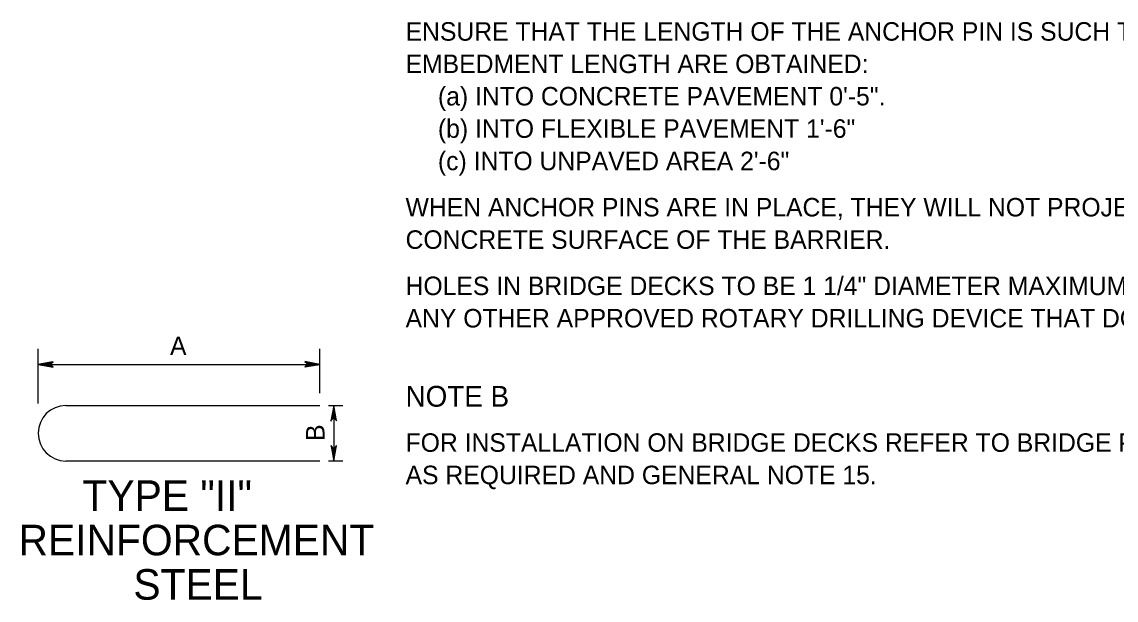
# Model space of a CAD drawing. Extents: x 499866 to 500993, y 499985 to 500645.
# Drawn here: x 500570.3 to 500807.1, y 500188.6 to 500313.6 of the extents above; entities that cross this region are included whole.
import ezdxf

# ---------------------------------------------------------------- set-up
doc = ezdxf.new("R2010")
doc.units = 0
doc.layers.add('24', color=7, linetype='Continuous')
doc.layers.add('5', color=7, linetype='Continuous')

msp = doc.modelspace()

# ---------------------------------------------------------------- linework, layer by layer
at = {"layer": '24'}
for points in [[(500573.87, 500239.55), (500577.15, 500238.97), (500576.37, 500239.55), (500577.13, 500240.12), (500573.87, 500239.55), (500574.09, 500239.56), (500577.06, 500239.01), (500576.3, 500239.56), (500577, 500240.07), (500574.21, 500239.57), (500574.32, 500239.55), (500576.86, 500239.1), (500576.29, 500239.56), (500576.87, 500240), (500574.37, 500239.55), (500574.48, 500239.57), (500576.7, 500239.17), (500576.26, 500239.55), (500576.71, 500239.95), (500574.79, 500239.57), (500574.98, 500239.57), (500576.53, 500239.25), (500576.23, 500239.54), (500576.56, 500239.87), (500575.01, 500239.55), (500575.18, 500239.54), (500576.35, 500239.34), (500576.13, 500239.57), (500576.37, 500239.79), (500575.35, 500239.55), (500575.51, 500239.53), (500576.21, 500239.4), (500576.1, 500239.56), (500576.29, 500239.73), (500575.6, 500239.55), (500576.05, 500239.44), (500575.99, 500239.57), (500576.19, 500239.69), (500575.71, 500239.57), (500576.01, 500239.49), (500575.89, 500239.59), (500576.03, 500239.65), (500575.89, 500239.56), (500575.96, 500239.54)], [(500634.83, 500239.55), (500631.55, 500240.13), (500632.34, 500239.55), (500631.57, 500238.98), (500634.83, 500239.55), (500634.61, 500239.54), (500631.65, 500240.09), (500632.4, 500239.54), (500631.7, 500239.03), (500634.49, 500239.53), (500634.38, 500239.55), (500631.84, 500240), (500632.41, 500239.54), (500631.83, 500239.1), (500634.33, 500239.55), (500634.23, 500239.53), (500632.01, 500239.93), (500632.44, 500239.55), (500632, 500239.15), (500633.91, 500239.53), (500633.72, 500239.53), (500632.17, 500239.85), (500632.47, 500239.56), (500632.15, 500239.23), (500633.69, 500239.55), (500633.52, 500239.56), (500632.35, 500239.76), (500632.57, 500239.53), (500632.33, 500239.31), (500633.36, 500239.55), (500633.19, 500239.57), (500632.49, 500239.7), (500632.6, 500239.54), (500632.41, 500239.37), (500633.11, 500239.55), (500632.65, 500239.66), (500632.71, 500239.53), (500632.51, 500239.41), (500632.99, 500239.53), (500632.69, 500239.61), (500632.82, 500239.51), (500632.67, 500239.45), (500632.82, 500239.54), (500632.74, 500239.56)], [(500637.83, 500230.65), (500637.23, 500227.3), (500637.83, 500228.1), (500638.41, 500227.32), (500637.83, 500230.65), (500637.83, 500230.43), (500637.28, 500227.39), (500637.83, 500228.16), (500638.36, 500227.45), (500637.84, 500230.31), (500637.83, 500230.2), (500637.36, 500227.6), (500637.83, 500228.18), (500638.29, 500227.58), (500637.83, 500230.14), (500637.84, 500230.03), (500637.43, 500227.76), (500637.83, 500228.2), (500638.23, 500227.75), (500637.84, 500229.71), (500637.84, 500229.52), (500637.52, 500227.93), (500637.82, 500228.24), (500638.15, 500227.91), (500637.83, 500229.49), (500637.81, 500229.31), (500637.61, 500228.11), (500637.84, 500228.34), (500638.07, 500228.09), (500637.83, 500229.14), (500637.81, 500228.98), (500637.67, 500228.26), (500637.83, 500228.38), (500638.01, 500228.18), (500637.83, 500228.89), (500637.71, 500228.42), (500637.84, 500228.49), (500637.97, 500228.28), (500637.84, 500228.77), (500637.77, 500228.46), (500637.87, 500228.59), (500637.93, 500228.44), (500637.83, 500228.59), (500637.82, 500228.51)], [(500637.83, 500218.66), (500638.42, 500222.01), (500637.83, 500221.21), (500637.24, 500221.99), (500637.83, 500218.66), (500637.82, 500218.88), (500638.37, 500221.92), (500637.82, 500221.15), (500637.29, 500221.86), (500637.81, 500219), (500637.83, 500219.11), (500638.29, 500221.71), (500637.82, 500221.13), (500637.36, 500221.73), (500637.83, 500219.16), (500637.81, 500219.28), (500638.22, 500221.55), (500637.83, 500221.11), (500637.42, 500221.56), (500637.81, 500219.6), (500637.81, 500219.79), (500638.13, 500221.38), (500637.83, 500221.07), (500637.5, 500221.4), (500637.83, 500219.82), (500637.84, 500220), (500638.04, 500221.2), (500637.81, 500220.97), (500637.58, 500221.22), (500637.83, 500220.16), (500637.84, 500220.33), (500637.98, 500221.05), (500637.82, 500220.93), (500637.64, 500221.13), (500637.83, 500220.42), (500637.94, 500220.89), (500637.81, 500220.82), (500637.68, 500221.03), (500637.81, 500220.54), (500637.89, 500220.85), (500637.78, 500220.72), (500637.72, 500220.87), (500637.82, 500220.72), (500637.83, 500220.8)]]:
    msp.add_lwpolyline(points, dxfattribs=at)
at = {"layer": '5'}
for p, q in [((500573.87, 500231.08), (500573.87, 500242.89)), ((500634.83, 500233.31), (500634.83, 500242.89)), ((500573.87, 500239.55), (500634.83, 500239.55)), ((500579.87, 500230.65), (500634.83, 500230.65)), ((500636.72, 500230.65), (500639.82, 500230.65)), ((500637.83, 500230.65), (500637.83, 500218.66)), ((500579.87, 500218.66), (500634.83, 500218.66)), ((500636.72, 500218.66), (500639.82, 500218.66))]:
    msp.add_line(p, q, dxfattribs=at)
msp.add_arc((500579.87, 500224.65), 6, 90, 270, dxfattribs=at)

# ---------------------------------------------------------------- texts
for s, height, p in [('ENSURE THAT THE LENGTH OF THE ANCHOR PIN IS SUCH THAT THE FOLLOWING MINIMUM ', 4, (500653.37, 500309.52)), ('EMBEDMENT LENGTH ARE OBTAINED:', 4, (500653.37, 500302.52)), ('(a) INTO CONCRETE PAVEMENT 0\'-5".', 4, (500660.37, 500295.52)), ('(b) INTO FLEXIBLE PAVEMENT 1\'-6"', 4, (500660.37, 500288.52)), ('(c) INTO UNPAVED AREA 2\'-6" ', 4, (500660.37, 500281.52)), ('WHEN ANCHOR PINS ARE IN PLACE, THEY WILL NOT PROJECT ABOVE THE PLANE OF THE', 4, (500653.37, 500271.52)), ('CONCRETE SURFACE OF THE BARRIER.', 4, (500653.37, 500264.52)), ('HOLES IN BRIDGE DECKS TO BE 1 1/4" DIAMETER MAXIMUM AND MADE WITH A CORE DRILL OR', 4, (500653.37, 500254.52)), ('ANY OTHER APPROVED ROTARY DRILLING DEVICE THAT DOES NOT IMPART AN IMPACT FORCE.', 4, (500653.37, 500247.52)), ('A', 4, (500602.4, 500241.55)), ('NOTE B', 4.5, (500653.37, 500230.39)), ('FOR INSTALLATION ON BRIDGE DECKS REFER TO BRIDGE PLANS FOR NECESSARY MODIFICATIONS', 4, (500653.37, 500220.64)), ('AS REQUIRED AND GENERAL NOTE 15.', 4, (500653.37, 500213.64)), ('TYPE "II" ', 6.6, (500583.46, 500207.87)), ('REINFORCEMENT', 6.6001, (500569.62, 500198.27)), ('STEEL', 6.6, (500594.47, 500188.67))]:
    msp.add_text(s, height=height, dxfattribs=at).set_placement(p)
msp.add_text('B', height=4, rotation=90, dxfattribs=at).set_placement((500635.83, 500222.99))

doc.saveas('drawing.dxf')
